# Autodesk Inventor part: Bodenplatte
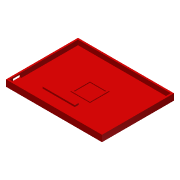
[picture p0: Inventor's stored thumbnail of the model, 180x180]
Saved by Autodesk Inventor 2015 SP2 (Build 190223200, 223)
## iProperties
Created: 2017-07
Material: ABS-rot
Document SubType Name: Modeling
Designer: UR
Density: 1.06 g/cm^3
Appearance: Glatt - weiß
Mass: 28.408 g
Surface Area: 277.04 cm^2
Volume: 26.8 cm^3
Part Number: Bodenplatte
Author: UR
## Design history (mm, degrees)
sketch "Skizze1"
  geometry: L1 (-60, 45)-(60, 45); L2 (60, 45)-(60, -45); L3 (60, -45)-(-60, -45); L4 (-60, -45)-(-60, 45); L5 (-84, 0)-(84, 0) reference; L6 (0, -63)-(0, 63) reference; 1 further point
  constraints: 8 end point, 2 parallel, 1 horizontal, 1 perpendicular, 2 other
  dimensions: "d0" = 120 distance of L1.start L1.end; "d1" = 90 distance of L3.end L1.start
extrude "Boden" new body sketch "Skizze1" distance "d2" = 2; taper "d3" = 0 deg
node "Mittelebene xz"
node "Mittelebene yz"
sketch "Skizze2"
  geometry: L1 (60, 45)-(-60, 45) reference; L2 (-60, 45)-(-60, -45) reference; L3 (-60, -45)-(60, -45) reference; L4 (60, -45)-(60, 45) reference; L5 (-58, 43)-(58, 43); L6 (58, 43)-(58, -43); L7 (58, -43)-(-58, -43); L8 (-58, -43)-(-58, 43); 1 further point
  constraints: 8 end point, 3 other
  dimensions: "d4" = 2 distance between parallel lines of L5 L1
extrude "Wand" join sketch "Skizze2" distance "d5" = 6; taper "d6" = 0 deg
sketch "Skizze3"
  geometry: L1 (-10, 10)-(10, 10); L2 (10, 10)-(10, -10); L3 (10, -10)-(-10, -10); L4 (-10, -10)-(-10, 10); L5 (0, -63)-(0, 63) reference; L6 (-84, 0)-(84, 0) reference; L7 (12, -12)-(12, 12); L8 (12, 12)-(-12, 12); L9 (-12, 12)-(-12, -12); L10 (-12, -12)-(12, -12); 1 further point
  constraints: 16 end point, 4 parallel, 3 perpendicular, 1 horizontal, 5 other
  dimensions: "d7" = 20 distance between parallel lines of L2 L4; "d8" = 2 distance between parallel lines of L7 L2
extrude "Quadrat für Magnetblech" join sketch "Skizze3" distance "d9" = 1; taper "d10" = 0 deg
sketch "Skizze4"
  geometry: L1 (2, 2)-(8, 2) reference; L2 (2, 88)-(2, 2) reference; L3 (6.2, 17.1)-(2, 17.1); L4 (2, 17.1)-(2, 6.9); L5 (2, 6.9)-(6.2, 6.9); L6 (6.2, 6.9)-(6.2, 17.1); L7 (2, 12)-(10.648, 12); 1 further point
  constraints: 10 end point, 2 horizontal, 2 parallel, 1 midpoint, 1 perpendicular, 1 point on line
  dimensions: "d12" = 10.2 distance between parallel lines of L5 L3; "d13" = 4.2 distance between parallel lines of L2 L6; "d36" = 10 distance between parallel lines of L1 L7
extrude "Durchbruch für Schieber" cut sketch "Skizze4" stored distance "d14" = 1; taper "d15" = 0 deg
sketch "Skizze7"
  geometry: L1 (7, -21)-(-33, -21); L2 (-33, -21)-(-33, -26); L3 (-33, -26)-(7, -26); L4 (7, -26)-(7, -21); L5 (-58, -38.1)-(-58, -27.9) reference; L6 (-60, -38.1)-(-58, -38.1) reference; L7 (-60, -27.9)-(-60, -38.1) reference; L8 (-60, -27.9)-(-58, -27.9) reference; L9 (-13, -21)-(-13, -26); L10 (-58, -33)-(-63.293, -33); 1 further point
  constraints: 12 end point, 3 midpoint, 2 horizontal, 2 parallel, 1 perpendicular
  dimensions: "d30" = 5 distance of L1.end L2.end; "d31" = 40 distance of L2.end L3.end; "d33" = 13 distance from line of L9 point (0, 0); "d37" = 7 distance between parallel lines of L10 L3
extrude "Steckverbindung Feder" join sketch "Skizze7" distance "d34" = 2; taper "d35" = 0 deg
node "Steckverbindung Mitte xz"
node "Steckverbindung Mitte yz"
node "Volumenkörper1"
node "Projizierte Kontur1"
node "Projizierte Kontur2"
